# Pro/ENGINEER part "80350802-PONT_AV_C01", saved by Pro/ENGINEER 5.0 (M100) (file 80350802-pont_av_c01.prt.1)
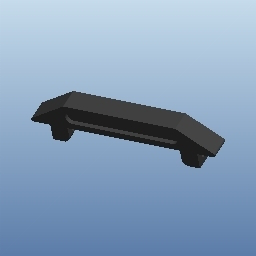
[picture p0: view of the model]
Units: millimeter Newton Second (mmNs); MM, TONNE, HOURS
Materials in the file: NYLON

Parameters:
  PTC_MATERIAL_NAME = "NYLON"

Other named items: DROITE, DESSUS, FACE, CS0, 80350802-PONT_AV_S01

Layers: 03_PLANS, 05_SURFACES, 06_REPERES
